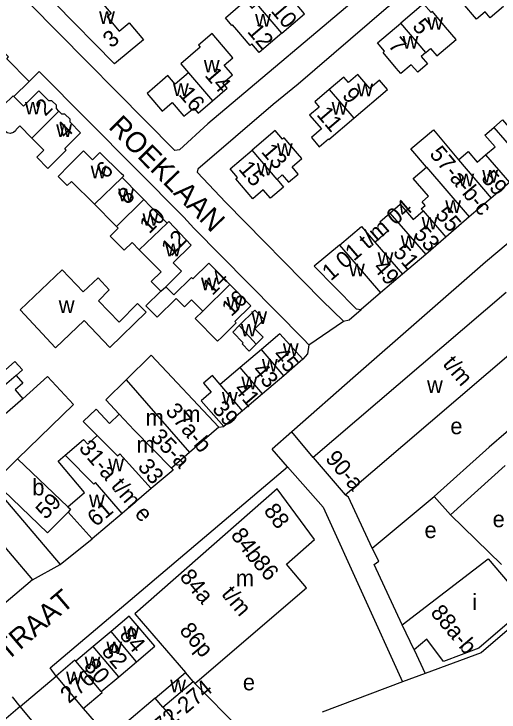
# Model space of a CAD drawing. Extents: x 161775 to 163181, y 382878 to 383925.
# Drawn here: x 162312.7 to 162431.4, y 383208.3 to 383379.1 of the extents above; entities that cross this region are included whole.
import ezdxf

# ---------------------------------------------------------------- set-up
doc = ezdxf.new("R2010")
doc.units = 0
for name, color, linetype in [('BLT_Basislijn', 7, 'Continuous'), ('BLT_Bebouwing', 7, 'Continuous'), ('BLT_Centroide', 7, 'Continuous'), ('BLT_Huisnummer', 7, 'Continuous'), ('BLT_Huisnummer_ tussenligend', 7, 'Continuous'), ('BLT_Huisnummer_reeks', 7, 'Continuous'), ('BLT_Onderdoorgang_en_onderverdeling', 7, 'Continuous'), ('BLT_Onderverdeling_panden', 7, 'Continuous'), ('BLT_Straatnaam', 7, 'Continuous'), ('BLT_Vlakafsluiter', 7, 'Continuous')]:
    doc.layers.add(name, color=color, linetype=linetype)

msp = doc.modelspace()

# ---------------------------------------------------------------- linework, layer by layer
at = {"layer": 'BLT_Basislijn'}
for p, q in [((162362.84, 383277.99), (162364.05, 383278.17)), ((162380.71, 383276.86), (162375.9, 383272.61)), ((162385.9, 383270.62), (162380.71, 383276.86)), ((162379.65, 383268.33), (162375.9, 383272.61)), ((162388.35, 383258.43), (162379.65, 383268.33)), ((162394.52, 383260.87), (162393.7, 383261.49)), ((162400.38, 383248.41), (162394.52, 383260.87)), ((162400.38, 383248.41), (162415.49, 383261.1)), ((162388.35, 383258.43), (162407.78, 383215.69)), ((162410.59, 383223.58), (162413.28, 383217.74)), ((162322.97, 383217.1), (162321.52, 383219.17)), ((162347.2, 383211.74), (162354.62, 383217.99)), ((162356.97, 383215.3), (162370.48, 383201.77)), ((162314.2, 383209.68), (162312.32, 383212.02)), ((162329.63, 383209.22), (162336.1, 383201.83))]:
    msp.add_line(p, q, dxfattribs=at)
for points in [[(162458.26, 383455.1), (162467.27, 383444.75), (162467.36, 383443.86), (162431.49, 383412.9), (162418.33, 383401.81), (162417.78, 383401.1), (162408.01, 383392.9), (162400.04, 383385.87), (162360.11, 383352.24), (162353.15, 383345.86), (162352.04, 383345.68), (162316.39, 383381.73), (162316.3, 383384.27), (162343.54, 383407.84), (162344.4, 383408.4), (162353.54, 383416.23), (162354.02, 383416.86), (162411.46, 383465.98), (162414.05, 383468.24), (162414.93, 383469.26), (162422.42, 383475.81)], [(162495.64, 383411.76), (162472.36, 383438.61), (162471.64, 383438.47), (162459.3, 383427.81), (162454.29, 383423.76), (162452.92, 383422.41), (162420.3, 383394.84), (162416.34, 383390.96), (162412.36, 383387.52), (162403.8, 383380.46), (162382.22, 383361.95), (162376.07, 383356.94), (162357.64, 383341.11), (162357.5, 383340.43), (162364.56, 383332.99), (162388.13, 383309.03), (162393.36, 383303.95)], [(162316.35, 383362.57), (162318.82, 383365.05), (162354.26, 383329.41), (162356.68, 383326.73), (162383.53, 383299.53), (162384.83, 383298.13)], [(162456.06, 383330.26), (162453.04, 383332.87), (162451.19, 383333.51), (162448.17, 383333.75), (162446.62, 383333.31), (162444.19, 383332.23), (162436.14, 383325.13), (162428.1, 383318.38), (162396.25, 383290.62), (162380.71, 383276.86)], [(162393.36, 383303.95), (162394.71, 383304.28), (162397.64, 383306.82)], [(162384.83, 383298.13), (162384.54, 383295.97), (162383.36, 383294.64)], [(162313.56, 383270.3), (162327.22, 383283.55), (162320.86, 383290.42), (162314.8, 383284.99)], [(162300.43, 383272.05), (162323.97, 383244.46)], [(162321.52, 383219.17), (162338.97, 383233.92), (162379.65, 383268.33)], [(162419.52, 383256.55), (162432.03, 383244.45)], [(162323.97, 383244.46), (162331.84, 383250.68)], [(162407.68, 383229.67), (162400.84, 383244.46), (162401.95, 383245.27), (162400.38, 383248.41)]]:
    msp.add_lwpolyline(points, dxfattribs=at)
at = {"layer": 'BLT_Bebouwing'}
for p, q in [((162316.35, 383362.57), (162312.66, 383358.89)), ((162433.92, 383337.86), (162429.46, 383334.04)), ((162429.46, 383334.04), (162424.1, 383329.45)), ((162424.1, 383329.45), (162418.37, 383324.47)), ((162418.37, 383324.47), (162413.45, 383320.24)), ((162413.45, 383320.24), (162407.75, 383315.47)), ((162407.75, 383315.47), (162402.36, 383310.86)), ((162433.18, 383310.99), (162385.9, 383270.62)), ((162402.36, 383310.86), (162397.64, 383306.82)), ((162393.7, 383261.49), (162440.98, 383301.87)), ((162373.27, 383297.03), (162368.04, 383292.58)), ((162383.36, 383294.64), (162378.69, 383290.56)), ((162368.04, 383292.58), (162363.15, 383288.42)), ((162378.69, 383290.56), (162373.51, 383286.16)), ((162373.51, 383286.16), (162368.61, 383282)), ((162314.8, 383284.99), (162306.21, 383277.49)), ((162368.61, 383282), (162364.05, 383278.17)), ((162362.84, 383277.99), (162355.62, 383271.8)), ((162355.62, 383271.8), (162351.2, 383268)), ((162385.9, 383270.62), (162393.7, 383261.49)), ((162313.56, 383270.3), (162325.85, 383258.55)), ((162346.28, 383262.98), (162339.13, 383256.9)), ((162339.13, 383256.9), (162331.84, 383250.68)), ((162340.9, 383231.79), (162336.42, 383228.02)), ((162336.42, 383228.02), (162332.07, 383224.34)), ((162332.07, 383224.34), (162327.84, 383220.75)), ((162413.28, 383217.74), (162407.78, 383215.69)), ((162322.97, 383217.1), (162329.63, 383209.22)), ((162337.84, 383217.52), (162337.85, 383217.53)), ((162349.08, 383209.54), (162356.5, 383215.83)), ((162407.78, 383215.69), (162388.07, 383208.33)), ((162347.2, 383211.74), (162340.3, 383205.83)), ((162320.88, 383201.8), (162314.2, 383209.68)), ((162349.08, 383209.54), (162355.12, 383202.5))]:
    msp.add_line(p, q, dxfattribs=at)
for points in [[(162432.49, 383380.96), (162429.22, 383378.17), (162428, 383379.6), (162425.89, 383377.81), (162422.51, 383381.78), (162419.27, 383385.59), (162421.86, 383387.8), (162421.22, 383388.55), (162424.01, 383390.92)], [(162341.1, 383370.08), (162337.23, 383366.91), (162322.63, 383381.72), (162322.74, 383383.1), (162328.81, 383388.22), (162332.04, 383384.4), (162336.43, 383379.21), (162335.45, 383378.38), (162338.42, 383374.87), (162340.86, 383376.93), (162344.38, 383372.77), (162341.1, 383370.08)], [(162378.23, 383374.41), (162383.81, 383379.17), (162381.99, 383381.29), (162382.3, 383381.56), (162379.06, 383385.36), (162378.02, 383386.57), (162375.69, 383384.58), (162374.1, 383386.44), (162371.64, 383384.33), (162373.22, 383382.48), (162372.13, 383381.55)], [(162378.23, 383374.41), (162372.66, 383369.65), (162370.86, 383371.76), (162370.45, 383371.4), (162367.2, 383375.2), (162366.16, 383376.42), (162366.03, 383376.31), (162364.43, 383378.18), (162369.33, 383382.37), (162370.91, 383380.51), (162372.13, 383381.55)], [(162413.5, 383369.7), (162414.65, 383370.68), (162416.2, 383368.84), (162420.91, 383372.85), (162418.31, 383375.89), (162415.07, 383379.7), (162414.76, 383379.44), (162412.93, 383381.59), (162407.39, 383376.88)], [(162413.5, 383369.7), (162412.35, 383368.73), (162413.9, 383366.9), (162411.48, 383364.84), (162409.91, 383366.69), (162407.37, 383364.53), (162406.25, 383365.85), (162403.01, 383369.66), (162403.38, 383369.98), (162401.66, 383372), (162407.39, 383376.88)], [(162361.29, 383357.87), (162364.84, 383360.91), (162363.77, 383362.16), (162366.14, 383364.19), (162364.11, 383366.58), (162366.23, 383368.39), (162361.18, 383374.31), (162357.84, 383371.46), (162358.23, 383371), (162353.47, 383366.94), (162355.36, 383364.73)], [(162316.35, 383362.57), (162310.93, 383368.14), (162311.36, 383368.61), (162308.3, 383371.65), (162307.88, 383371.27), (162306.56, 383372.55), (162303.62, 383369.69), (162303.29, 383369.98), (162300.19, 383366.98)], [(162355.36, 383364.73), (162352.1, 383361.94), (162350.33, 383364.02), (162349.03, 383362.91), (162345.23, 383359.67), (162348.9, 383355.36), (162351.37, 383357.47), (162354.28, 383354.06), (162356.66, 383356.09), (162357.73, 383354.84), (162361.29, 383357.87)], [(162395.82, 383353.61), (162404.06, 383360.65), (162402.13, 383362.92), (162399.75, 383360.89), (162396.85, 383364.29), (162394.55, 383362.33), (162393.41, 383363.66), (162389.85, 383360.63)], [(162323.68, 383355.34), (162323.05, 383355.97), (162323.06, 383356.75), (162321.96, 383357.86), (162321.19, 383357.86), (162318.77, 383360.31), (162314.97, 383356.55), (162312.66, 383358.89)], [(162389.85, 383360.63), (162386.28, 383357.6), (162387.35, 383356.34), (162385.02, 383354.36), (162387.92, 383350.96), (162385.45, 383348.86), (162387.38, 383346.59), (162389.66, 383348.52), (162389.75, 383348.41), (162395.82, 383353.61)], [(162317.01, 383348.74), (162319.95, 383345.77), (162318.23, 383344.06), (162320.94, 383341.33), (162321.92, 383342.3), (162325.47, 383345.82), (162325.12, 383346.17), (162328.98, 383350), (162326.38, 383352.63), (162326.38, 383353.36), (162325.13, 383354.62), (162324.39, 383354.62), (162323.68, 383355.34)], [(162430.11, 383351.32), (162432.27, 383353.17), (162434.75, 383350.28), (162436.91, 383352.14)], [(162317.01, 383348.74), (162314.07, 383351.71), (162313.22, 383350.87), (162313.05, 383350.5), (162312.54, 383350.07), (162311.7, 383349.86), (162311.01, 383350.02), (162310.54, 383350.39), (162310.33, 383350.78), (162310.19, 383351.32), (162309.44, 383352), (162307.32, 383349.81), (162305.87, 383351.23)], [(162428.11, 383344.62), (162430.41, 383346.6), (162427.95, 383349.47), (162430.11, 383351.32)], [(162377.05, 383338.62), (162378.34, 383339.73), (162379.88, 383337.92), (162382.26, 383339.95), (162380.75, 383341.73), (162383.09, 383343.72), (162382.04, 383344.96), (162378.8, 383348.77), (162378.43, 383348.45), (162376.58, 383350.62), (162370.93, 383345.81)], [(162413.61, 383341.64), (162409.83, 383346.07), (162415.34, 383350.77), (162421.44, 383343.44)], [(162377.05, 383338.62), (162378.62, 383336.77), (162375.44, 383334.06), (162373.7, 383336.11), (162371.1, 383333.89), (162366.96, 383338.74), (162367.39, 383339.1), (162365.56, 383341.25), (162370.93, 383345.81)], [(162338.93, 383340.09), (162333.66, 383345.22), (162331.87, 383343.44), (162329.72, 383345.61), (162326.17, 383342.09), (162323.44, 383339.38), (162325.7, 383337.11), (162326.75, 383338.15), (162332.34, 383332.54)], [(162421.44, 383343.44), (162423.82, 383345.49), (162426.08, 383342.88), (162428.11, 383344.62)], [(162412.84, 383330.91), (162412.35, 383331.47), (162413.29, 383332.28), (162412.55, 383333.13), (162414.15, 383334.51), (162410.39, 383338.88), (162413.61, 383341.64)], [(162339.16, 383339.07), (162339.56, 383339.47), (162338.93, 383340.09)], [(162344.44, 383333.7), (162343.42, 383334.8), (162339.16, 383339.07)], [(162344.44, 383333.7), (162346.03, 383332.08), (162350.15, 383327.92)], [(162332.34, 383332.54), (162337.35, 383327.48), (162337.78, 383327.1)], [(162404.7, 383330.41), (162407.17, 383332.54), (162410.38, 383328.8), (162412.84, 383330.91)], [(162400.99, 383323.31), (162404.17, 383326.04), (162402.24, 383328.29), (162404.7, 383330.41)], [(162337.78, 383327.1), (162338.19, 383326.69), (162336.21, 383324.73), (162339.63, 383321.28), (162341.57, 383323.19), (162343.34, 383321.4)], [(162350.15, 383327.92), (162350.54, 383328.31), (162356.03, 383322.58), (162351.64, 383318.22), (162353.68, 383316.16), (162349.82, 383312.33)], [(162392.33, 383322.57), (162397.73, 383327.1), (162400.99, 383323.31)], [(162392.33, 383322.57), (162386.17, 383317.41), (162396.44, 383306.95), (162397.64, 383306.82)], [(162348.58, 383311.3), (162346.27, 383313.63), (162348.68, 383316.02), (162343.34, 383321.4)], [(162349.82, 383312.33), (162351.76, 383310.36), (162356.11, 383314.67), (162356.47, 383314.31), (162360.33, 383318.14), (162365.46, 383312.91)], [(162365.46, 383312.91), (162370.6, 383307.69), (162366.76, 383303.89), (162367.07, 383303.58), (162363.51, 383300.06), (162362.5, 383299.05), (162357.02, 383304.59), (162358.86, 383306.41)], [(162358.86, 383306.41), (162356.1, 383309.19), (162354.37, 383307.48), (162352.34, 383309.53), (162347.71, 383304.94), (162344.96, 383307.72), (162348.58, 383311.3)], [(162367.82, 383302.9), (162371.63, 383306.68)], [(162371.63, 383306.68), (162373.88, 383304.35), (162371.6, 383302.09), (162373.66, 383300.01), (162371.92, 383298.29)], [(162371.92, 383298.29), (162370.25, 383296.64), (162368.51, 383298.39), (162368.8, 383298.67), (162366.2, 383301.3), (162367.82, 383302.9)], [(162383.36, 383294.64), (162377.77, 383300.85), (162373.27, 383297.03)], [(162340.14, 383289.59), (162346.25, 383295.6), (162362.84, 383277.99)], [(162453.92, 383294.69), (162428.95, 383273.17), (162415.49, 383261.1)], [(162313.19, 383290.69), (162314.72, 383292.01), (162312.91, 383294.1), (162307.48, 383289.37), (162305.67, 383291.44)], [(162313.19, 383290.69), (162314.83, 383288.81), (162312.92, 383287.15), (162314.8, 383284.99)], [(162338.45, 383281.19), (162335.13, 383284.67), (162340.14, 383289.59)], [(162363.15, 383288.42), (162361.23, 383290.68), (162359.02, 383288.8), (162360.95, 383286.55), (162358.51, 383284.48), (162364.05, 383278.17)], [(162333.01, 383275.99), (162329.61, 383279.4), (162332.75, 383282.4), (162336.07, 383278.92), (162338.45, 383281.19)], [(162325.19, 383271.17), (162329.7, 383274.97), (162330.73, 383273.84), (162333.01, 383275.99)], [(162325.85, 383258.55), (162329.96, 383262.04), (162323.45, 383269.69), (162325.19, 383271.17)], [(162313.56, 383270.3), (162307.79, 383264.65), (162320.87, 383252.21), (162325.95, 383257.24)], [(162351.2, 383268), (162351.61, 383267.52), (162346.28, 383262.98)], [(162419.52, 383256.55), (162432.86, 383268.63)], [(162356.97, 383215.3), (162384.25, 383238.76), (162379.4, 383244.5), (162386.25, 383250.58), (162377.05, 383262.92), (162342.28, 383232.35), (162354.62, 383217.99)], [(162415.49, 383261.1), (162419.52, 383256.55)], [(162331.84, 383250.68), (162325.95, 383257.24)], [(162307.2, 383252.45), (162317.2, 383240.64)], [(162407.68, 383229.67), (162428.77, 383245.83), (162438.52, 383234.33), (162426.43, 383223.98), (162417.76, 383220.74), (162413.7, 383226.17), (162410.59, 383223.58)], [(162317.2, 383240.64), (162268.02, 383198.98), (162258.01, 383210.79), (162259, 383211.62)], [(162439.08, 383233.21), (162426.99, 383222.86), (162413.28, 383217.74)], [(162347.13, 383224.42), (162340.9, 383231.79)], [(162410.59, 383223.58), (162407.68, 383229.67)], [(162342.66, 383220.66), (162347.13, 383224.42)], [(162327.84, 383220.75), (162327.6, 383221.02), (162322.97, 383217.1)], [(162338.3, 383216.98), (162342.66, 383220.66)], [(162334.04, 383213.39), (162338.3, 383216.98)], [(162356.5, 383215.83), (162356.97, 383215.3)], [(162329.63, 383209.22), (162334.27, 383213.12), (162334.04, 383213.39)], [(162314.2, 383209.68), (162309.63, 383205.82)]]:
    msp.add_lwpolyline(points, dxfattribs=at)
msp.add_lwpolyline([(162322.83, 383297.42), (162314.14, 383306.72), (162324.47, 383316.5), (162329.59, 383311.09), (162333.24, 383314.54), (162335.99, 383311.64), (162333.38, 383308.96), (162338.38, 383303.69), (162342.89, 383308.24), (162344.99, 383306.16), (162336.1, 383297.52), (162329.85, 383304.09)], close=True, dxfattribs=at)
at = {"layer": 'BLT_Onderdoorgang_en_onderverdeling'}
msp.add_line((162413.61, 383341.64), (162424.1, 383329.45), dxfattribs=at)
at = {"layer": 'BLT_Onderverdeling_panden'}
for p, q in [((162378.23, 383374.41), (162372.13, 383381.55)), ((162413.5, 383369.7), (162407.39, 383376.88)), ((162355.36, 383364.73), (162361.29, 383357.87)), ((162389.85, 383360.63), (162395.82, 383353.61)), ((162317.01, 383348.74), (162323.68, 383355.34)), ((162430.11, 383351.32), (162438.42, 383341.65)), ((162377.05, 383338.62), (162370.93, 383345.81)), ((162428.11, 383344.62), (162433.92, 383337.86)), ((162421.44, 383343.44), (162429.46, 383334.04)), ((162332.34, 383332.54), (162339.16, 383339.07)), ((162337.78, 383327.1), (162344.44, 383333.7)), ((162404.7, 383330.41), (162413.45, 383320.24)), ((162412.84, 383330.91), (162418.37, 383324.47)), ((162350.15, 383327.92), (162343.34, 383321.4)), ((162392.33, 383322.57), (162402.36, 383310.86)), ((162400.99, 383323.31), (162407.75, 383315.47)), ((162348.58, 383311.3), (162349.82, 383312.33)), ((162358.86, 383306.41), (162365.46, 383312.91)), ((162367.82, 383302.9), (162371.92, 383298.29)), ((162378.69, 383290.56), (162373.27, 383297.03)), ((162373.51, 383286.16), (162368.04, 383292.58)), ((162313.19, 383290.69), (162302.65, 383281.58)), ((162340.14, 383289.59), (162355.62, 383271.8)), ((162368.61, 383282), (162363.15, 383288.42)), ((162342.66, 383220.66), (162336.42, 383228.02)), ((162338.3, 383216.98), (162332.07, 383224.34)), ((162334.04, 383213.39), (162327.84, 383220.75)), ((162356.5, 383215.83), (162354.62, 383217.99)), ((162349.08, 383209.54), (162347.2, 383211.74))]:
    msp.add_line(p, q, dxfattribs=at)
for points in [[(162312.66, 383358.89), (162312.45, 383359.11), (162310.09, 383356.78)], [(162338.45, 383281.19), (162342.07, 383277.25), (162351.2, 383268)], [(162333.01, 383275.99), (162338, 383271.02), (162338.57, 383271.48), (162346.28, 383262.98)], [(162339.13, 383256.9), (162332.64, 383264.52), (162332.2, 383264.12), (162325.19, 383271.17)], [(162325.85, 383258.55), (162326.5, 383257.93), (162325.95, 383257.24)]]:
    msp.add_lwpolyline(points, dxfattribs=at)
at = {"layer": 'BLT_Vlakafsluiter'}
for p, q in [((162384.83, 383298.13), (162393.36, 383303.95)), ((162317.2, 383240.64), (162323.97, 383244.46)), ((162314.2, 383209.68), (162322.97, 383217.1))]:
    msp.add_line(p, q, dxfattribs=at)

# ---------------------------------------------------------------- texts
at = {"layer": 'BLT_Centroide'}
for s, p in [('w', (162333.5, 383376.67)), ('w', (162371.69, 383376)), ('w', (162413.84, 383375.22)), ('w', (162407.78, 383370.64)), ('w', (162359.14, 383364.78)), ('w', (162351.58, 383359.03)), ('w', (162396.67, 383358.94)), ('w', (162315.34, 383354.53)), ('w', (162390.42, 383354.47)), ('w', (162323, 383349.02)), ('w', (162377.02, 383344.39)), ('w', (162372.09, 383339.59)), ('w', (162331.45, 383338.88)), ('w', (162427.29, 383337.84)), ('w', (162421.44, 383336.95)), ('w', (162338.16, 383333.28)), ('w', (162418.23, 383330.44)), ('w', (162344.12, 383327.28)), ('w', (162412.45, 383326.38)), ('w', (162407.34, 383321.88)), ('w', (162349.69, 383319.8)), ('w', (162401.67, 383317.75)), ('w', (162394.67, 383314.91)), ('w', (162358.45, 383311.53)), ('w', (162364.7, 383306.77)), ('w', (162323.62, 383305.94)), ('w', (162370.75, 383303.29)), ('w', (162368.19, 383300.22)), ('w', (162378.48, 383295.47)), ('w', (162373.36, 383291.61)), ('w', (162368.33, 383287.3)), ('w', (162413.77, 383286.41)), ('w', (162363.56, 383283.56)), ('m', (162344.88, 383278.38)), ('m', (162353.86, 383279.25)), ('e', (162419.48, 383276.3)), ('m', (162342.66, 383271.81)), ('w', (162335.73, 383267.23)), ('b', (162317.15, 383261.34)), ('w', (162331.03, 383258.42)), ('e', (162429.83, 383253.55)), ('e', (162413.15, 383250.89)), ('m', (162366.96, 383239.12)), ('i', (162424.85, 383233.28)), ('w', (162339.42, 383226.22)), ('w', (162335.29, 383222.5)), ('w', (162329.96, 383218.84)), ('w', (162325.43, 383215.11)), ('w', (162350.9, 383213.16)), ('e', (162368.69, 383213.65))]:
    msp.add_text(s, height=4, dxfattribs=at).set_placement(p)
at = {"layer": 'BLT_Huisnummer'}
for s, rotation, p in [('10', 310.4835, (162375.38, 383379.77)), ('5', 310.4035, (162409.98, 383375.95)), ('12', 310.482, (162369.59, 383374.73)), ('7', 310.4086, (162404.07, 383371.32)), ('14', 310.5011, (162359.18, 383364.02)), ('16', 310.4783, (162352.8, 383359.33)), ('9', 310.3998, (162392.81, 383359.08)), ('2', 44.7106, (162320.31, 383353.91)), ('11', 310.3982, (162386.55, 383354.42)), ('4', 44.7106, (162325.32, 383348.36)), ('13', 310.3932, (162373.01, 383345.33)), ('6', 44.7324, (162335.13, 383338.56)), ('15', 310.4053, (162367.45, 383341.09)), ('8', 44.7324, (162340.41, 383332.27)), ('55', 310.6722, (162415.58, 383329.91)), ('10', 44.7272, (162345.78, 383325.15)), ('12', 44.7272, (162351.07, 383319.62)), ('51', 310.6697, (162405.26, 383320.66)), ('16', 44.7226, (162365.86, 383304.89)), ('45', 310.3676, (162375.86, 383295.55)), ('41', 310.3676, (162366.32, 383287.18)), ('39', 310.3693, (162361, 383282.37)), ('33', 310.3711, (162342.76, 383268.26)), ('59', 46.0248, (162320.42, 383255.25)), ('61', 40.3589, (162332.74, 383253.5)), ('84', 310.2119, (162338.27, 383227.06)), ('80', 310.2119, (162329.56, 383219.43)), ('276', 40.2619, (162326.11, 383210.31))]:
    msp.add_text(s, height=4, rotation=rotation, dxfattribs=at).set_placement(p)
at = {"layer": 'BLT_Huisnummer_ tussenligend'}
for s, rotation, p in [('53', 310.6697, (162410.28, 383325.15)), ('49', 310.6697, (162400.39, 383316.91)), ('14', 44.7288, (162361.2, 383310.05)), ('43', 310.3676, (162370.81, 383291.8)), ('82', 310.2119, (162333.92, 383223.1))]:
    msp.add_text(s, height=4, rotation=rotation, dxfattribs=at).set_placement(p)
at = {"layer": 'BLT_Huisnummer_reeks'}
for s, rotation, p in [('3', 39.3362, (162336.48, 383370.59)), ('57-a-b-c', 309.807, (162414.19, 383344.77)), ('59', 310.6699, (162426.84, 383338.79)), ('1 01 t/m 04', 40.6696, (162390.21, 383313.65)), ('t/m', 310.5632, (162417.43, 383293.4)), ('37a-b', 310.3677, (162349.54, 383281.87)), ('35-a', 313.8703, (162345.88, 383275.36)), ('31-a t/m e', 310.3651, (162328.36, 383272.82)), ('90-a', 310.5624, (162388.68, 383270.24)), ('88', 306.712, (162373.64, 383257.55)), ('84b', 306.712, (162365.57, 383251.57)), ('86', 310.2129, (162370.93, 383244.65)), ('84a', 310.2009, (162353.03, 383241.27)), ('t/m', 310.2129, (162363.26, 383237.11)), ('88a-b', 310.2864, (162414.43, 383232.54)), ('86p', 310.2009, (162352.98, 383228.18)), ('272-274', 40.2167, (162346.59, 383200.85))]:
    msp.add_text(s, height=4, rotation=rotation, dxfattribs=at).set_placement(p)
at = {"layer": 'BLT_Straatnaam'}
for s, height, rotation, p in [('ROEKLAAN', 5, 314.6612, (162335.56, 383351.27)), ('TONGELRESESTRAAT', 4.9999, 40.4764, (162272.83, 383188.14))]:
    msp.add_text(s, height=height, rotation=rotation, dxfattribs=at).set_placement(p)

doc.saveas('drawing.dxf')
